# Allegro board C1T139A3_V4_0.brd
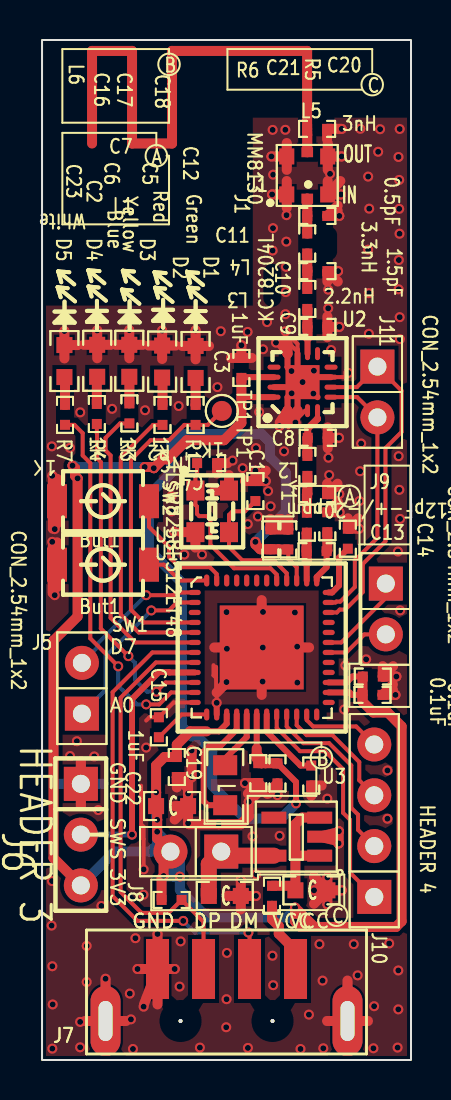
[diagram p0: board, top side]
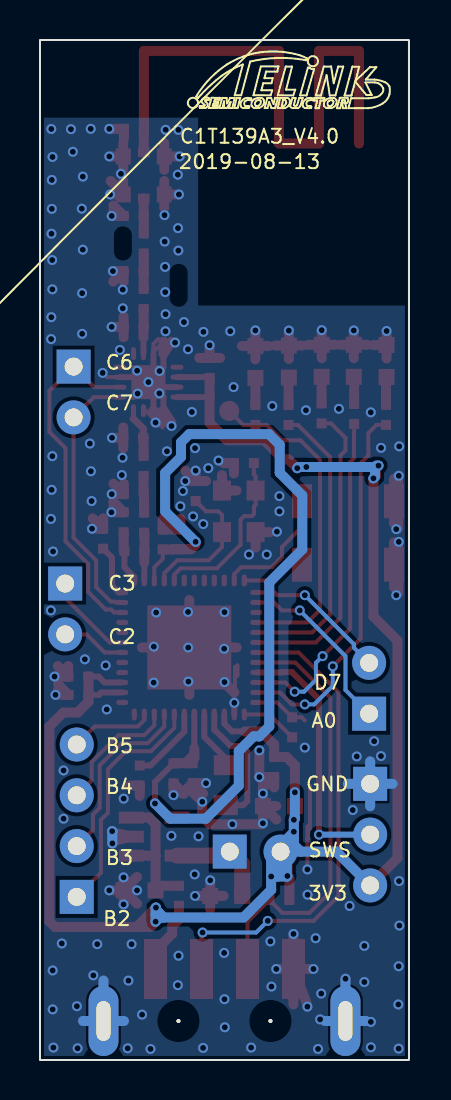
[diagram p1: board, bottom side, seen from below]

Outline 18.45 x 51 mm; copper layers: TOP, BOTTOM. Coordinates in mm from the lower left corner of the outline.
Outline path: rectangle 0,0 18.45,51

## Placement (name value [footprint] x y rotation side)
C1  NC  [0402]  10.67 28.45 90 top
C2  2.2uF  [0402]  12.31 26.03 270 top
C3  1uF  [0402]  9.97 34.6 270 top
C4  NC  [0402]  8.26 29.84 0 top
C5  18pF  [0402]  14.27 26.89 90 top
C6  220pF  [0402]  13.24 26.87 90 top
C7  NC  [0402]  13.76 28.29 180 top
C8  NC  [0402]  13.79 31.11 180 top
C9  1.8pF  [0402]  13.77 36.66 180 top
C10  1.5pF  [0402]  13.77 39.44 180 top
C11  0.5pF  [0402]  13.76 42.2 180 top
C12  1uF  [0402]  15.29 26.06 90 top
C13  0.1uF  [0402]  16.53 18.26 0 top
C14  0.1uF  [0402]  16.54 19.17 0 top
C15  1uF  [0402]  5.84 16.64 90 top
C16  1uF  [0402]  10.81 14.34 90 top
C17  0.1uF  [0402]  11.77 14.33 90 top
C18  1uF  [0402]  13.46 14.22 270 top
C19  0.1uF  [0402]  6.74 14.65 90 top
C20  10uF  [0603C]  13.47 8.48 0 top
C21  10uF  [0603C]  9.14 8.2 0 top
C22  10uF  [0603C]  6.5 12.7 0 top
C23  0.1uF  [0402]  11.42 26.04 270 top
D1  Green  [0603-LED]  7.68 34.9 90 top
D2  Red  [0603-LED]  6.01 34.92 90 top
D3  Yellow  [0603-LED]  4.36 34.96 90 top
D4  Blue  [0603-LED]  2.76 34.96 90 top
D5  White  [0603-LED]  1.12 34.95 90 top
J1  MM8130  [MM8130-2600]  13.26 44.23 180 top
J5  CON_2.54mm_1x2  [HDR254F-1X2X850]  1.99 19.86 270 top
J6  HEADER 3  [HDR254M-1X3]  1.94 13.81 270 top
J7  USB_SMT_4PIN  [USB-M-4]  9.22 4.55 90 top
J8  B2S  [HDR254F-1X2X850]  6.42 10.42 0 top
J9  CON_2.54mm_1x2  [HDR254F-1X2X850]  17.19 21.28 90 top
J10  HEADER 4  [HDR254F-1X4X850]  16.61 15.78 270 top
J11  CON_2.54mm_1x2  [HDR254F-1X2X850]  16.77 32.13 90 top
L1  1.3nH  [0402]  13.73 25.44 180 top
L2  000R  [0402]  13.27 29.71 90 top
L3  2.2nH  [0402]  13.26 38.05 90 top
L4  3.3nH  [0402]  13.26 40.82 90 top
L5  3nH  [0402]  13.75 46.56 0 top
L6  47uH  [0805L]  9.16 13.74 270 top
R1  1K  [0402]  7.68 32.25 90 top
R2  1K  [0402]  6.02 32.25 90 top
R3  1K  [0402]  4.37 32.33 90 top
R4  1K  [0402]  2.74 32.3 90 top
R5  10  [0402]  11.5 8.21 90 top
R6  NC/1.5K  [0402]  6.48 8 0 top
R7  1K  [0402]  1.15 32.26 90 top
SW1  But1  [BUTSMD2PX4_00Y3_00_NH]  3.05 24.77 270 top
SW2  But1  [BUTSMD2PX4_00Y3_00_NH]  3.05 27.94 270 top
TP1  A2  [TP100]  8.99 32.45 0 top
U1  TLSR8258F512ET48  [QFN_7X7_48PIN_0P5_4P20X4P20]  10.98 20.63 0 top
U2  KCT8204L  [QFN_3X3_16PIN_0P5_1P70X1P70]  13.03 33.89 90 top
U3  XC6219_3.3V_SOT-23-5  [SOT-23-5]  12.74 11.17 90 top
Y1  24MHz-12pF-+/-20ppm  [OSCCC200X250X080]  8.51 27.43 0 top

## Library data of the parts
C1 C4 = C1005_NC
C2 C13 C14 C23 = C1005X5R1C104K
C3 C6-C11 = C1608_NC
C5 = C1005C0G1H100D
C12 = C1608X5R1C105M
C15-C17 C19 = C1005X5R1C105K
C18 C20-C22 = C1608X5R0J106M
D1-D5 = 0603D_Red
J1 = MM8130
J5 J9 J11 = CON_2.54mm_1x2: User Part Number: pn; Tolerance: RichardLC
J6 = HEADER 3: User Part Number: pn; Tolerance: RichardLC
J7 = USB_SMT_1
J8 = B2S_0: User Part Number: pn; Tolerance: RichardLC
J10 = HEADER_4: User Part Number: pn; Tolerance: RichardLC
L1-L4 = MLK1608_000R
L5 = MLK1005S1N5ST
L6 = IND_0
R1-R4 R7 = RS0402K332JT
R5 R6 = RS0402K100JT
SW1 SW2 = SW2PIN_3x4
TP1 = TestPad100
U1 = TLSR8258F512ET48
U2 = RFX2401C_7
U3 = XC6219_1.3V_SOT-23-5
Y1 = OSC_25x32_4pin

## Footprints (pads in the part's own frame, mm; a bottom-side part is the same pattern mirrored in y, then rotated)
0402
  rect 0.5x0.5 smd: 1(-0.5,0) 2(0.5,0)
0603-LED
  rect 0.8x0.8 smd: A(-0.8,0) C(0.8,0)
0603C
  rect 0.8x0.8 smd: 1(-0.8,0) 2(0.8,0)
0805L
  rect 1x1.2 smd: 1(-1,0) 2(1,0)
BUTSMD2PX4_00Y3_00_NH
  rect 1.7x1 smd: 1(0,2.3) 2(0,-2.3)
HDR254F-1X2X850
  rect 1.7x1.7 hole 0.9: 1(2.54,0)
  round 1.7 hole 0.9: 2(0,0)
HDR254F-1X4X850
  rect 1.7x1.7 hole 0.9: 1(7.62,0)
  round 1.7 hole 0.9: 2(5.08,0) 3(2.54,0) 4(0,0)
HDR254M-1X3
  rect 1.7x1.7 hole 0.9: 1(0,0)
  round 1.7 hole 0.9: 2(2.54,0) 3(5.08,0)
MM8130-2600
  rect 0.58x0.5 smd: 1(0,1.16) 2(0,-1.16)
  rect 0.75x0.8 smd: 3(-1.025,0.95) 4(1.025,0.95) 5(-1.025,-0.95) 6(1.025,-0.95)
OSCCC200X250X080
  rect 0.9x1 smd: 1(-0.84,1.04) 2(-0.84,-1.04) 3(0.84,-1.04) 4(0.84,1.04)
QFN_3X3_16PIN_0P5_1P70X1P70
  oval 0.65x0.25 smd: 1(-1.425,0.75) 2(-1.425,0.25) 3(-1.425,-0.25) 4(-1.425,-0.75) 9(1.425,-0.75) 10(1.425,-0.25) 11(1.425,0.25) 12(1.425,0.75)
  oval 0.25x0.65 smd: 5(-0.75,-1.425) 6(-0.25,-1.425) 7(0.25,-1.425) 8(0.75,-1.425) 13(0.75,1.425) 14(0.25,1.425) 15(-0.25,1.425) 16(-0.75,1.425)
  rect 1.7x1.7 smd: 17(0,0)
QFN_7X7_48PIN_0P5_4P20X4P20
  oval 0.6x0.26 smd: 1(-3.35,2.75) 2(-3.35,2.25) 3(-3.35,1.75) 4(-3.35,1.25) 5(-3.35,0.75) 6(-3.35,0.25) 7(-3.35,-0.25) 8(-3.35,-0.75) 9(-3.35,-1.25) 10(-3.35,-1.75) 11(-3.35,-2.25) 12(-3.35,-2.75) 25(3.35,-2.75) 26(3.35,-2.25) 27(3.35,-1.75) 28(3.35,-1.25) 29(3.35,-0.75) 30(3.35,-0.25) 31(3.35,0.25) 32(3.35,0.75) 33(3.35,1.25) 34(3.35,1.75) 35(3.35,2.25) 36(3.35,2.75)
  oval 0.26x0.6 smd: 13(-2.75,-3.35) 14(-2.25,-3.35) 15(-1.75,-3.35) 16(-1.25,-3.35) 17(-0.75,-3.35) 18(-0.25,-3.35) 19(0.25,-3.35) 20(0.75,-3.35) 21(1.25,-3.35) 22(1.75,-3.35) 23(2.25,-3.35) 24(2.75,-3.35) 37(2.75,3.35) 38(2.25,3.35) 39(1.75,3.35) 40(1.25,3.35) 41(0.75,3.35) 42(0.25,3.35) 43(-0.25,3.35) 44(-0.75,3.35) 45(-1.25,3.35) 46(-1.75,3.35) 47(-2.25,3.35) 48(-2.75,3.35)
  rect 4.2x4.2 smd: 49(0,0)
SOT-23-5
  rect 0.6x1.25 smd: 1(-0.95,-1.145) 2(0,-1.145) 3(0.95,-1.145) 4(0.95,1.145) 5(-0.95,1.145)
TP100
  round 1 smd: 1(0,0)
USB-M-4
  round 0.2 hole 1.7 unplated: (-2.6,2.3) (-2.6,-2.3)
  rect 3x1.15 smd: 1(0,-3.45) 2(0,-1.15) 3(0,1.15) 4(0,3.45)
  oval 3.5x1.5 hole 2x0.7: S1(-2.6,6.05) S2(-2.6,-6.05)

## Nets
3V3: C3.2 C13.1 C14.1 C19.2 C22.1 J6.3 J8.2 R6.1 U1.15(VDD_IO) U1.26(VDD3) U1.27(VDDIO_AMS) U2.14(VDD#14) U2.16(VDD#16)
GND: C1.2 C2.1 C3.1 C4.2 C5.2 C7.1 C8.1 C9.1 C10.1 C11.1 C12.2 C13.2 C14.2 C15.2 C16.1 C17.1 C18.2 C19.1 C20.2 C21.2 C22.2 C23.1 D1.C(CATHODE) D2.C(CATHODE) D3.C(CATHODE) D4.C(CATHODE) D5.C(CATHODE) J1.3 J1.4 J1.5 J1.6 J6.1 J7.4(GND) J7.S1 J7.S2 L5.2 SW1.2 SW2.2 U1.12(DVSS#12) U1.14(DVSS#14) U1.49(GND) U2.1(BYPASS) U2.2(GND#2) U2.3(GND#3) U2.7(GND#7) U2.11(ANT_SEL) U2.12(GND#12) U2.15(GND#15) U2.17(GND#17) U3.2(VSS) Y1.2 Y1.4
VBUS: C20.1 R5.2 U3.1(VIN) U3.3(CE)
TL_1V2: C2.2 C16.2 C17.2 C23.2 U1.18(VDD1V2) U1.39(AVDD1V2)
TL_A0: J5.1 U1.2(DMIC_DI/P0N/URX/A[0])
TL_A2: R1.1 TP1.1(TP) U1.4(DO/UTX/P0/A[2])
TL_A3: R2.1 U1.5(DI/UCTS/P1/A[3])
TL_A4: R3.1 U1.6(CK/URTS/P2/A[4])
TL_ANT: C6.1 L1.2 U1.38(ANT)
TL_B0: R4.1 U1.10(P3/URX/ATSEL1/B[0])
TL_B1: R7.1 U1.11(P4/UTX/ATSEL2/B[1])
TL_B2: J10.1 U1.20(P5/UCTS/CYC2LNA/B[2])
TL_B3: J10.2 U1.21(P0N/URTS/CYC2PA/B[3])
TL_B4: J10.3 U1.22(SDMP0/P4/B[4])
TL_B5: J10.4 U1.23(SDMN0/P5/B[5])
TL_C2: J9.2 U1.30(P0/7816TRX/I2CSDA/32KO/PGAP1/C[)
TL_C3: J9.1 U1.31(P1/URX/I2CCK/32KI/PGAN1/C[3])
TL_C6: J11.1 U1.34(CYC2LNA/ATSEL1/P4N/C[6]) U2.6(RXEN)
TL_C7: J11.2 U1.35(CYC2PA/ATSEL2/P5N/C[7]) U2.5(TXEN)
TL_D5: SW2.1 U1.47(P0/P0N/D[5])
TL_D6: SW1.1 U1.48(CN/URX/ATSEL0/D[6])
TL_D7: J5.2 U1.1(CK/I2SBCK/7816TRX/D[7])
TL_DM: J7.2(D-) U1.7(DM/A[5])
TL_DP: J7.3(D+) R6.2 U1.8(DP/A[6])
TL_SWS/A7: J6.2 U1.9(SWS/URTS/A[7])
TL_XC1: C1.1 U1.40(XC1) Y1.3
TL_XC2: C4.1 U1.41(XC2) Y1.1
N14798367: C18.1 U1.19(VDD_F)
N14798471: L6.1 U1.17(VDCDC)
N14798499: L6.2 U1.16(VDCDC_SW)
N14798557: C15.1 U1.13(VDD1V)
N14798729: C12.1 U1.36(RESETB)
N14798779: C5.1 L1.1 U1.37(VANT)
N14803016: C6.2 C7.2 L2.1
N14803042: C8.2 L2.2 U2.4(TXRX)
N14803152: C10.2 L3.2 L4.1
N14803180: C9.2 L3.1 U2.10(ANT1)
N14803220: C11.2 J1.1 L4.2
N14803264: J1.2 L5.1
N14807404: D1.A(ANODE) R1.2
N14807456: D3.A(ANODE) R3.2
N14807480: D4.A(ANODE) R4.2
N14807598: D2.A(ANODE) R2.2
N14823075: C21.1 J8.1 U3.5(VOUT)
N14823079: J7.1(5V) R5.1
N14826545: D5.A(ANODE) R7.2

Pads without a net: U1 3 24 25 28 29 32 33 42 43 44 45 46; U2 8 9 13; U3 4

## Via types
v1: diameter 0.5, hole 0.3, TOP to BOTTOM, 207 vias

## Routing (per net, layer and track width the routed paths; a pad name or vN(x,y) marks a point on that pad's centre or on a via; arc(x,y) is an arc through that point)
3V3: length 99.4
  TOP w0.3: U1.15 9.23,16.82 8.85,16.43 8.22,16.43 ; C13.1 15.51,18.26 15.39,18.38 U1.26 ; U2.16 9.99,33.14 9.97,33.12 ; C14.1 15.52,19.17 15.22,18.88 U1.27 ; U2.14 10.01,34.14 C3.2
  TOP w0.5: R6.1 5.98,9.1 v1(6.08,9.2) 6.08,10.08 J8.2 5.76,11.08 v1(5.76,11.41) v1(5.76,12.01) 5.76,12.64 C22.1 v1(5.7,13.39) 5.7,14.73 6.12,15.15 C19.2 6.74,15.77 7.4,16.43 8.22,16.43 ; v1(5.13,29.65) 5.53,29.65 v1(5.59,29.59) 6.03,30.03 6.28,30.03 7.24,30.99 9.1,30.99 9.97,31.86 C3.2 ; 13.62,6.65 17.7,6.65 17.98,6.94 17.98,16.68 17.29,17.37 16.57,17.37 16.03,17.92 C13.1 16.03,19.16 C14.1 ; 13.62,6.65 12.67,7.6 ; 13.62,6.65 12.93,6.65 v1(12.67,6.92) 12.67,7.6 ; v1(1.52,29.72) 1.65,29.59 1.65,29.21 v1(1.78,29.08) 1.78,22.18 0.58,20.97 0.58,10.09 J6.3 ; 12.67,7.6 v1(12.65,7.62)
  BOTTOM w0.5: 6.58,9.17 v1(6.89,9.17) ; 6.58,9.17 6.11,9.17 ; 6.58,9.17 6.42,9.33 J8.2 ; v1(6.89,9.17) 6.89,9.95 J8.2 ; v1(6.89,9.17) 6.89,8.51 8.27,7.13 12.27,7.13 ; 12.51,7.37 12.65,7.51 v1(12.65,7.62) 12.67,7.6 12.67,7.29 ; 12.51,7.37 12.6,7.29 12.67,7.29 ; 12.51,7.37 12.27,7.13 ; 6.11,9.17 v1(6.08,9.2) ; 6.11,9.17 6.11,10.11 J8.2 ; 12.27,7.13 12.46,7.13 v1(12.67,6.92) 12.67,7.29 ; J8.2 5.41,10.42 ; J8.2 6.42,10.73 5.76,11.39 ; J8.2 5.76,11.08 ; v1(5.59,29.59) 5.53,29.65 v1(5.13,29.65) 1.7,29.65 ; 5.41,10.42 3.63,10.42 J6.3 ; 5.41,10.42 5.76,10.76 5.76,11.08 ; 1.7,29.65 1.7,29.16 v1(1.78,29.08) ; 1.7,29.65 1.63,29.72 v1(1.52,29.72) ; 5.76,11.08 5.76,11.39 ; 5.76,11.39 v1(5.76,11.41) v1(5.76,12.01) 5.7,12.06 v1(5.7,13.39)
GND: length 161.6
  TOP w0.2: U2.7 15.11,34.14 v1(15.32,34.35) ; 8.69,19.66 8.7,19.65 8.7,19.1 ; U2.11 12.78,35.41 ; 12.78,35.41 12.78,35.81 12.53,36.05 ; 12.78,35.41 12.28,35.91 ; U2.3 13.16,32.47 12.32,31.62 ; 8.7,19.1 8.7,18.41 8.73,18.38 v1(8.73,17.86) ; 8.7,19.1 8.57,19.23 8.57,19.74 ; 5.08,11.05 v1(5.08,9.53) ; 5.08,11.05 5.05,11.08 5.05,11.5 4.95,11.59 4.95,13.72 ; 5.08,11.05 5.08,11.66 5,11.74 ; 5.21,16.97 5.37,17.14 C15.2 6.58,17.88 U1.12
  TOP w0.25: 12.28,31.95 12.78,32.45 U2.2
  TOP w0.3: U2.2 12.78,33.64 ; 12.78,33.64 U2.15 ; 12.78,33.64 12.28,33.14 U2.1 ; 12.78,33.64 U2.17 ; U2.11 12.78,34.14 ; 12.78,34.14 U2.17 ; 12.78,34.14 12.28,34.64 U2.12 ; 13.78,33.14 U2.17 ; U2.17 13.28,34.14 U2.7 ; U1.14 v1(8.73,17.86)
  TOP w0.5: 0.75,23.64 SW1.2 0.75,25.89 ; 11.79,27.05 C2.1 ; C2.1 12.31,27.05 ; C2.1 11.43,26.53 C23.1 ; C21.2 v1(9.94,8.98) ; C21.2 v1(10.7,8.2) ; C21.2 9.27,8.2 ; C21.2 9.94,7.53 ; 11.88,35.91 U2.12 12.28,35.91 ; J1.6 12.24,45.85 ; J1.6 v1(11.47,45.18) ; J1.6 12.24,44.51 ; D2.C 6.68,35.72 ; D2.C v1(6.01,36.47) ; D2.C 5.34,35.72 ; D2.C 6.01,35.05 ; J1.4 12.24,43.95 ; J1.4 12.24,42.61 ; J1.4 v1(11.5,43.28) ; C14.2 17.56,19.69 ; C14.2 v1(17.72,19.17) ; C14.2 17.04,19.69 ; C22.2 v1(7.3,13.32) 7.3,13.97 v1(7.48,14.15) ; C22.2 6.63,12.02 ; C22.2 6.63,12.7 ; C22.2 v1(7.3,11.84) 7.35,11.79 v1(8.83,11.79) 9.95,11.79 10.34,12.18 v1(10.34,12.91) 10.81,13.39 C16.1 ; J7.S1 4.2,1.95 ; J7.S1 2.15,1.95 ; J7.S1 3.17,3.97 ; 15.28,1.95 15.28,3.97 ; 15.28,1.95 14.25,1.95 ; 15.28,1.95 16.3,1.95 ; 13.6,7.81 C20.2 ; C20.2 v1(14.27,7.78) ; C20.2 v1(14.27,9.13) ; C20.2 v1(13.6,8.48) ; C20.2 13.6,9.15 ; C20.2 v1(14.99,8.48) ; 10.98,18.26 U1.49 ; U1.49 8.73,18.38 ; U1.49 13.35,20.63 ; U1.49 8.61,20.63 ; U1.49 10.98,23 ; C3.1 v1(9.97,35.74) ; C3.1 10.49,35.1 ; C3.1 9.45,35.1 ; 14.49,11.17 14.57,11.17 14.83,11.43 ; 14.49,11.17 U3.2 ; 14.49,11.17 v1(14.83,10.83) 14.83,11.43 ; J1.3 14.29,43.95 ; J1.3 14.92,43.95 ; J1.3 v1(14.95,43.28) ; 12.08,31.87 U2.1 ; U2.1 11.88,31.87 ; U2.1 v1(12.67,31.87) ; C23.1 11.42,27.06 ; C23.1 11.94,27.06 ; 13.98,13.72 C18.2 13.46,13.2 ; 6.74,13.63 C19.1 ; C19.1 v1(7.48,14.15) ; C19.1 7.26,13.63 ; C7.1 v1(14.86,28.29) ; C7.1 14.26,28.81 ; C7.1 14.78,28.81 ; v1(14.84,11.44) 14.83,11.43 ; 0.54,29.2 0.54,26.57 ; 9.28,29.84 C4.2 8.76,29.32 ; 2.76,35.09 D4.C ; D4.C 3.43,35.76 ; D4.C v1(2.76,36.48) ; D4.C 2.09,35.76 ; C16.1 11.34,13.32 ; C16.1 v1(10.15,13.84) ; C16.1 10.29,13.32 ; 4.36,35.09 D3.C ; D3.C 3.69,35.76 ; D3.C 5.03,35.76 ; D3.C v1(4.36,36.49) ; U3.2 14.78,11.38 ; U3.2 14.78,10.95 ; C10.1 v1(14.8,39.44) ; C10.1 14.79,38.92 ; C10.1 14.27,38.92 ; C9.1 14.27,37.18 ; C9.1 v1(14.87,36.66) ; C9.1 14.27,36.14 ; 0.75,29.06 SW2.2 0.75,26.82 ; C12.2 15.29,27.08 ; C12.2 v1(15.85,26.56) ; C12.2 15.81,27.08 ; D5.C 1.79,35.75 ; D5.C 1.12,35.08 ; D5.C v1(1.12,36.45) ; C13.2 17.55,18.52 ; C13.2 v1(17.67,18.26) ; C13.2 17.55,18.78 ; 1.94,12.69 J6.1 1.94,14.93 ; C8.1 14.29,31.63 ; C8.1 v1(14.85,31.11) ; C8.1 14.29,30.59 ; C5.2 v1(14.88,27.39) ; C5.2 14.79,27.91 ; C5.2 14.79,27.65 ; 14.29,44.51 J1.5 ; J1.5 v1(14.98,45.18) ; J1.5 14.29,45.85 ; 5.78,4.55 v1(6.63,4.55) ; 5.78,4.55 v1(4.78,4.55) ; 5.78,4.55 v1(5.78,6.3) ; 5.78,4.55 5.1,2.78 ; 5.78,4.55 5.78,2.78 ; D1.C v1(7.68,36.48) ; D1.C 7.68,35.03 ; D1.C 8.35,35.7 ; D1.C 7.01,35.7 ; C11.1 v1(14.86,42.2) ; C11.1 14.78,42.46 ; C11.1 14.78,42.72 ; 11.25,13.31 C17.1 11.77,13.31 ; C1.2 11.19,29.47 ; C1.2 v1(11.19,28.95) ; C1.2 10.15,28.95 ; C1.2 v1(10.67,29.47) ; 12.38,31.87 U2.2 12.58,31.87 ; 9.35,29.24 Y1.4 8.63,28.47 ; v1(14.98,46.56) L5.2 14.25,46.04 ; 7.67,25.62 7.67,26.39 6.95,26.39 ; v1(7.48,14.15) v1(7.48,15.48) ; 0.53,25.66 0.53,23.35
  BOTTOM w0.5: J6.1 3.06,13.81 ; J6.1 0.82,13.81 ; J6.1 1.94,14.93 ; J6.1 1.94,12.69 ; 2.15,1.95 J7.S1 ; J7.S1 3.17,3.97 ; J7.S1 4.2,1.95 ; 15.28,1.95 16.3,1.95 ; 15.28,1.95 15.28,3.97 ; 15.28,1.95 14.25,1.95 ; v1(14.84,11.44) 14.83,11.43 v1(14.83,10.83)
  vias: v1(0.49,30.68) v1(0.51,29.21) v1(0.51,25.91) v1(0.5,8.95) v1(0.48,6.72) v1(0.51,4.69) v1(0.53,2.78) v1(0.51,0.57) v1(0.64,26.54) v1(0.64,23.24) v1(1.4,30.61) v1(1.4,15.2) v1(1.74,15.94) v1(1.91,32.38) v1(1.91,1.91) v1(1.91,0.64) v1(2.23,5.7) v1(2.23,3.9) v1(2.61,15.18) v1(2.81,12.5) v1(2.97,7.7) v1(3.17,4.06) v1(3.5,32.56) v1(4.39,3.32) v1(4.45,2.03) v1(4.55,0.55) v1(4.67,6.09) v1(5.07,8.26) v1(5.08,2.67) v1(5.15,32.49) v1(5.21,15.62) v1(6.48,28.19) v1(6.48,27.43) v1(6.6,26.42) v1(6.83,32.7) v1(6.93,5.93) v1(6.88,3.67) v1(7.11,25.27) v1(7.89,0.62) v1(8,25.27) v1(8.77,33.64) v1(8.94,36.44) v1(9.23,22.39) v1(9.24,20.56) v1(9.23,18.9) v1(9.24,5.35) v1(9.23,3.04) v1(9.21,1.64) v1(9.53,29.97) v1(10.03,29.59) v1(10.28,36.41) v1(10.29,26.8) v1(10.3,0.6) v1(10.52,11.18) v1(10.7,30.59) v1(10.72,9.28) v1(10.79,27.18) v1(10.86,32.4) v1(11.05,35.54) v1(11.05,22.4) v1(11.04,20.62) v1(11.03,18.92) v1(11.25,36.9) v1(11.3,28.45) v1(11.43,27.69) v1(11.53,46.51) v1(11.55,41.59) v1(11.53,40.47) v1(11.52,5.21) v1(11.56,44.27) v1(11.56,3.74) v1(11.7,35.87) v1(11.77,13.24) v1(11.87,31.7) v1(11.88,11.21) v1(12.1,30.44) v1(12.17,46.51) v1(12.22,42.24) v1(12.21,40.92) v1(12.2,39.66) v1(12.19,38.39) v1(12.17,37.29) v1(12.18,36.44) v1(12.47,34.45) v1(12.48,33.33) v1(12.64,22.38) v1(12.76,20.67) v1(12.77,18.87) v1(12.92,0.55) v1(13.03,33.9) v1(13.35,2.27) v1(13.59,34.47) v1(13.57,33.32) v1(13.87,5.79) v1(14.03,3.97) v1(14.06,0.59) v1(14.31,38.52) v1(14.31,37.58) v1(14.32,30.11) v1(14.27,13.07) v1(14.4,44.31) v1(14.36,29.25) v1(14.46,35.5) v1(15.11,17.53) v1(15.17,19.73) v1(15.59,5.79) v1(15.78,4.23) v1(15.91,46.56) v1(15.9,29.44) v1(15.87,27.95) v1(15.96,30.82) v1(16.21,20.03) v1(16.31,44.17) v1(16.31,40.52) v1(16.34,38.34) v1(16.34,36.31) v1(16.36,42.57) v1(16.61,2.69) v1(16.57,0.59) v1(16.81,45.41) v1(16.9,46.54) v1(17.27,14.48) v1(17.27,12.06) v1(17.36,5.83) v1(17.82,45.15) v1(17.84,40) v1(17.83,38.53) v1(17.83,30.19) v1(17.8,25.42) v1(17.82,4.48) v1(17.82,2.53) v1(17.78,0.62) v1(17.89,46.55) v1(17.86,44) v1(17.86,42.56) v1(17.88,41.31) v1(17.89,37.14) v1(17.89,36.05) v1(17.87,28.51) v1(17.9,27.05) v1(17.91,22.48)
VBUS: length 7.1
  TOP w0.5: U3.1 12.67,10.22 ; 12.67,10.22 C20.1 12.44,8.71 R5.2 ; 12.67,10.22 12.67,11.79 13,12.12 13.88,12.12 U3.3
TL_1V2: length 46
  TOP w0.2: C2.2 12.31,25.06 12.73,24.64 U1.39
  TOP w0.3: v1(12.7,12.83) 12.7,13.9 C17.2 ; U1.18 10.73,15.57 ; C16.2 10.73,15.27
  TOP w0.5: 10.98,14.84 10.73,15.09 10.73,15.27 ; 10.98,14.84 10.98,14.84 11.17,14.84 ; 10.98,14.84 C16.2 ; v1(10.67,25.91) 10.67,25.78 10.91,25.54 C23.2 11.81,25.54 11.82,25.53 C2.2 ; 10.73,15.57 10.73,15.27 ; 10.73,15.27 11.17,14.84 ; 11.17,14.84 11.76,14.84 C17.2
  BOTTOM w0.5: v1(12.7,12.83) 11.94,12.06 10.16,12.06 8.51,13.72 8.51,15.44 7.77,16.18 7.49,16.18 6.99,16.68 6.99,23.88 5.33,25.53 5.33,28.23 6.46,29.36 6.46,30.76 7,31.29 10.99,31.29 11.4,30.88 11.4,30.15 12.19,29.36 12.19,27.43 v1(10.67,25.91)
TL_A0: length 8.9
  TOP w0.2: v1(5.46,22.48) 6.35,22.48 6.75,22.88 U1.2
  BOTTOM w0.2: v1(5.46,22.48) 3.17,20.19 3.17,18.5 J5.1
TL_A2: length 16.5
  TOP w0.2: TP1.1 8.29,31.75 R1.1 7.12,31.75 6.35,30.99 5.43,30.99 4.45,30 4.45,22.51 5.08,21.88 U1.4
TL_A3: length 14.7
  TOP w0.2: R2.1 5.55,31.75 3.94,30.14 3.94,22.27 4.83,21.38 U1.5
TL_A4: length 15.3
  TOP w0.2: R3.1 3.9,31.83 3.17,31.11 3.17,30.48 3.43,30.23 3.43,22.11 4.66,20.88 U1.6
TL_ANT: length 2.4
  TOP w0.3: U1.38 13.23,24.88
  TOP w0.5: 13.23,24.88 13.23,25.44 L1.2 13.23,26.35 C6.1
TL_B0: length 17
  TOP w0.2: v1(5.71,18.41) 6.17,18.87 6.64,18.87 6.65,18.88 U1.10 ; v1(4.32,20.19) 2.94,21.57 2.94,29.9 2.75,30.09 2.75,31.32 2.74,31.33 R4.1
  BOTTOM w0.2: v1(4.32,20.19) 4.65,19.86 4.65,19.01 5.25,18.41 v1(5.71,18.41)
TL_B1: length 18.9
  TOP w0.2: v1(3.81,19.68) 2.41,21.08 2.41,29.84 2.03,30.23 2.03,31.35 1.62,31.76 R7.1 ; v1(5.21,17.78) 5.86,17.78 6.45,18.38 6.75,18.38 U1.11
  BOTTOM w0.2: v1(3.81,19.68) 3.81,18.71 4.74,17.78 v1(5.21,17.78)
TL_B2: length 11.9
  TOP w0.2: U1.20 11.73,16.61 12.9,15.44 14.15,15.44 15.05,14.54 15.05,12.36 15.4,12.01 15.4,11.34 15.4,11.34 15.4,9.36 J10.1
TL_B3: length 9.2
  TOP w0.2: J10.2 15.8,11.51 15.8,12.27 15.46,12.61 15.46,14.73 14.35,15.84 13.06,15.84 12.23,16.67 U1.21
TL_B4: length 6.4
  TOP w0.2: J10.3 15.86,13.99 15.86,14.9 14.52,16.24 13.23,16.24 12.73,16.74 U1.22
TL_B5: length 4.2
  TOP w0.2: J10.4 15.71,16.68 13.56,16.68 13.23,17 U1.23
TL_C2: length 3.2
  TOP w0.2: U1.30 15.22,20.38 16.12,21.28 J9.2
TL_C3: length 4.5
  TOP w0.2: U1.31 14.96,20.88 17.19,23.1 J9.1
TL_C6: length 17.5
  TOP w0.2: U1.34 14.74,22.38 14.89,22.52 15.16,22.52 16.04,23.4 16.04,24.8 17.17,25.93 17.17,30.6 17.98,31.4 17.98,33.46 J11.1 15.74,33.64 U2.6
TL_C7: length 13.3
  TOP w0.2: U1.35 14.67,22.88 14.72,22.92 14.91,22.92 15.64,23.65 15.64,24.98 16.77,26.11 J11.2 15.76,33.14 U2.5
TL_D5: length 6.3
  TOP w0.2: U1.47 8.73,24.3 8.39,24.64 6.87,24.64 6.48,25.03 6.35,25.16 6.35,25.65 5.35,26.66 SW2.1
TL_D6: length 3.2
  TOP w0.2: U1.48 6.88,23.98 6.1,24.77 SW1.1
TL_D7: length 7.2
  TOP w0.2: U1.1 6.72,23.38 6.58,23.24 v1(5.21,23.24)
  BOTTOM w0.2: v1(5.21,23.24) 2.75,20.78 2.75,20.61 J5.2
TL_DM: length 24.5
  TOP w0.2: v1(10.32,6.37) 10.38,6.32 J7.2 ; v1(7.06,6.96) 4.77,6.96 3.53,8.2 3.53,17.83 3.53,18.39 5.52,20.38 U1.7
  BOTTOM w0.2: v1(10.32,6.37) 7.64,6.37 v1(7.06,6.96)
TL_DP: length 21.8
  TOP w0.2: J7.3 8.07,6.91 R6.2 6.33,7.36 4.97,7.36 3.93,8.4 3.93,18.11 5.69,19.88 U1.8
TL_SWS/A7: length 13
  TOP w0.3: v1(4.5,11.27) 4.5,18.05 5.85,19.4 6.34,19.4 6.36,19.38 U1.9
  BOTTOM w0.3: J6.2 v1(4.5,11.27)
TL_XC1: length 7
  TOP w0.2: U1.40 12.23,24.34 11.59,24.99 10.01,24.99 9.35,25.65 Y1.3 9.35,27.26 9.53,27.43 10.14,27.43 10.44,27.73 10.45,27.73 C1.1
TL_XC2: length 8.9
  TOP w0.2: U1.41 11.73,24.27 11.42,24.59 9.6,24.59 8.42,25.77 8.42,27.02 8.24,27.19 7.86,27.19 7.75,27.3 7.75,27.67 7.67,27.75 7.67,29.19 7.75,29.28 C4.1
N14798367: length 3.8
  TOP w0.3: U1.19 11.23,16.42 12.93,14.72 C18.1
N14798471: length 3
  TOP w0.3: L6.1 9.16,15.08 9.64,15.56 10.23,16.15 U1.17
N14798499: length 6.5
  TOP w0.3: L6.2 8.29,12.74 8.08,12.95 8.08,15.41 8.37,15.7 8.91,15.7 9.73,16.52 U1.16
N14798557: length 2.9
  TOP w0.2: U1.13 6.98,17.28 C15.1
N14798729: length 2.7
  TOP w0.3: U1.36 14.5,23.38 14.85,23.72 14.85,25.12 C12.1
N14798779: length 2.6
  TOP w0.3: L1.1 14.23,24.64 13.73,24.15 U1.37
  TOP w0.5: C5.1 14.27,25.48 L1.1
N14803016: length 1.8
  TOP w0.5: C6.2 13.24,28.28 C7.2 13.27,28.31 L2.1
N14803042: length 2.5
  TOP w0.25: 13.78,32.06 U2.4
  TOP w0.35: C8.2 13.29,31.57 13.78,32.06 13.78,32.06
  TOP w0.5: L2.2 13.27,31.09 C8.2 13.28,31.12
N14803152: length 1.8
  TOP w0.5: L3.2 13.26,39.44 C10.2 13.26,39.45 L4.1
N14803180: length 2.2
  TOP w0.3: 13.28,36.13 U2.10
  TOP w0.5: 13.28,36.13 13.28,36.65 C9.2 13.27,37.55 L3.1
N14803220: length 1.7
  TOP w0.5: L4.2 13.26,42.2 C11.2 13.26,43.07 J1.1
N14803264: length 29.7
  TOP w0.5: 2.5,45.83 2.5,50.45 4.5,50.45 4.5,45.83 6.5,45.83 6.5,50.45 13.25,50.45 L5.1 13.26,46.25 J1.2
N14807404: length 1.3
  TOP w0.5: R1.2 7.68,32.76 D1.A
N14807456: length 1.3
  TOP w0.5: D3.A 4.37,34.15 R3.2
N14807480: length 1.4
  TOP w0.5: D4.A 2.74,34.14 R4.2
N14807598: length 1.4
  TOP w0.5: D2.A 6.02,34.1 R2.2
N14823075: length 5.2
  TOP w0.8: U3.5 9.16,10.22 J8.1 8.34,9.8 C21.1
N14823079: length 3.6
  TOP w0.5: R5.1 11.5,7.04 11.84,6.7 11.84,6.31 12.68,5.47 J7.1
N14826545: length 1.4
  TOP w0.5: D5.A 1.15,34.12 R7.2

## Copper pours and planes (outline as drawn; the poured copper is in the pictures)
GND on TOP: 0.2,0.2 0.2,37.72 10.54,37.72 10.54,47.12 18.25,47.12 18.25,0.2 ; 10 cut-outs
GND on BOTTOM: 0.2,0.2 0.2,37.72 10.54,37.72 10.54,47.12 18.25,47.12 18.25,0.2 ; 1 cut-out

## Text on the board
Ref Des/Silkscreen Bottom: D7 | A0 | SWS | 3V3 | GND | C1T139A3_V4.0 | 2019-08-13 | C3 | C2 | C6 | C7 | B5 | B4 | B3 | B2
Ref Des/Silkscreen Top: A | B | C | D7 | A0 | GND | SWS | 3V3
COMPVAL_TYPE_TOP: B | 1.5pF | A
User.6: FIGURE | SIZE | 0.3 | 0.9 | 1.7 | 2.0x0.7 | DRILL CHART: TOP to BOTTOM | ALL UNITS ARE IN MILLIMETERS | PLATED | NON-PLATED | QTY | 211 | 15 | 2
